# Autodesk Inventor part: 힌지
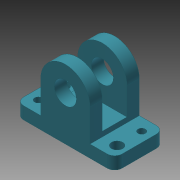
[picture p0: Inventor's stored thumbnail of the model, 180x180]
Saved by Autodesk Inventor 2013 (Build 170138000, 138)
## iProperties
Created: 2019-09
Part Number: 힌지
Material: 알루미늄 6061
Document SubType Name: Modeling
Designer: mduedu
Density: 1 g/cm^3
Author: mduedu
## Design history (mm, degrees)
sketch "스케치1"
  geometry: L1 (-20, 0)-(20, 0); L2 (20, 0)-(20, 5); L3 (-20, 5)-(-20, 0); L4 (10, 5)-(10, 18); L5 (-10, 18)-(-10, 5); L6 (20, 5)-(10, 5); L7 (-10, 5)-(-20, 5); C1 r 4.5 at (0, 18); A1 r 10 centre (0, 18) between (10, 18) and (-10, 18); 2 further points
  constraints: 14 end point, 4 parallel, 2 centre point, 2 coincident, 2 point on circle, 2 tangent, 1 collinear, 1 horizontal, 1 midpoint, 1 perpendicular, 1 vertical, 1 vertical alignment
  dimensions: "d0" = 40 distance of L1.start L1.end; "d2" = 20 distance between parallel lines of L4 L5; "d3" = 18 distance from line of L1 A1.centre; "d4" = 5 distance of L1.end L2.end; "d5" = 9 diameter of C1
extrude "돌출1" new body sketch "스케치1" stored distance "d6" = 20; taper "d7" = 0 deg
sketch "스케치2"
  geometry: L1 (7, 5)-(37, 5); L2 (37, 5)-(37, -5); L3 (37, -5)-(7, -5); L4 (7, -5)-(7, 5); L5 (0, 10)-(0, -10) reference; 2 further points
  constraints: 8 end point, 2 parallel, 1 horizontal, 1 horizontal alignment, 1 midpoint, 1 perpendicular
  dimensions: "d8" = 7 distance between parallel lines of L5 L4; "d9" = 10 distance of L1.end L2.end; "d10" = 30 distance of L2.end L3.end
extrude "돌출2" cut sketch "스케치2" stored distance "d11" = 20; taper "d12" = 0 deg
sketch "스케치3"
  geometry: 3 further points
  dimensions: "d13" = 16 horizontal distance of point (6, 15) point (-10, 10); "d14" = 32 horizontal distance of point (-26, 5) point (6, 15); "d15" = 5 vertical distance of point (6, 15) point (-10, 10); "d16" = 10 vertical distance of point (-26, 5) point (6, 15)
hole "구멍1" sketch "스케치3" at (6, 15), (-26, 5) diameter "d17" = 3; stored, may be unused: countersink angle "d21" = 90 deg, drill point angle "d23" = 118 deg; dims "d18" = 6, "d19" = 4, "d20" = 2, "d22" = 8
sketch "스케치4"
  geometry: C1 r 1.5 at (6, 15) reference; C2 r 1.5 at (-26, 5) reference; 3 further points
  constraints: 2 horizontal alignment, 2 vertical alignment
hole "구멍2" sketch "스케치4" at (-26, 15), (6, 5) diameter "d24" = 4.5; stored, may be unused: countersink angle "d28" = 90 deg, drill point angle "d30" = 118 deg; dims "d25" = 6, "d26" = 4, "d27" = 2, "d29" = 8
fillet "모깎기1" dims "d31" = 3
node "솔리드1"
